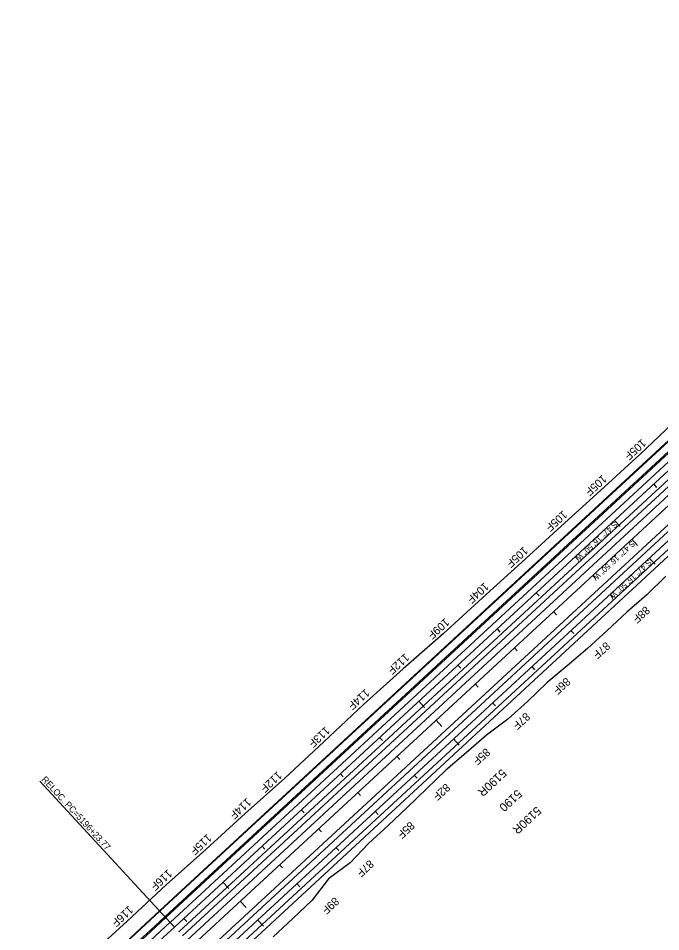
# Model space of a CAD drawing. Extents: x 2160876 to 2175625, y 601634 to 617693.
# Drawn here: x 2170102 to 2171308, y 612093 to 613806 of the extents above; entities that cross this region are included whole.
import ezdxf

# ---------------------------------------------------------------- set-up
doc = ezdxf.new("R2010")
doc.units = 0
for name, color, linetype in [('RD_HC_Cl', 7, 'Continuous'), ('RD_HC_CL_Rel', 7, 'Continuous'), ('RD_HC_Data', 7, 'Continuous'), ('RD_HC_Data_Rel', 7, 'Continuous'), ('RD_HC_Data_Tic', 7, 'Continuous'), ('RD_HC_Data_Tic_Rel', 7, 'Continuous'), ('RD_HC_TX_Rel_Sta50', 7, 'Continuous'), ('RD_HC_TX_Sta50', 7, 'Continuous'), ('RD_PD_CstnLmt', 7, 'Continuous'), ('RD_PD_Final_LnLine', 7, 'Continuous'), ('RD_PD_Final_TrvlWay', 7, 'Continuous'), ('RD_PD_GR', 7, 'Continuous'), ('RD_PD_MedBWall', 7, 'Continuous')]:
    doc.layers.add(name, color=color, linetype=linetype)

msp = doc.modelspace()

# ---------------------------------------------------------------- linework, layer by layer
at = {"layer": 'RD_HC_Cl'}
msp.add_line((2172239.9, 613739.9), (2163704.8, 605858.6), dxfattribs=at)
at = {"layer": 'RD_HC_CL_Rel'}
for p, q in [((2172207.3, 613775.1), (2170395.2, 612101.8)), ((2172272.5, 613704.6), (2170460.3, 612031.3))]:
    msp.add_line(p, q, dxfattribs=at)
msp.add_arc((2245020.2, 531286.6), 110000, 132.719474, 133.338342, dxfattribs=at)
at = {"layer": 'RD_HC_Data_Rel'}
msp.add_line((2170142.5, 612375.5), (2170395.2, 612101.8), dxfattribs=at)
at = {"layer": 'RD_HC_Data_Tic'}
for p, q in [((2171253.4, 612828.9), (2171264.2, 612817.2)), ((2171179.9, 612761.1), (2171185.3, 612755.2)), ((2171106.4, 612693.2), (2171111.8, 612687.3)), ((2171032.9, 612625.4), (2171038.4, 612619.5)), ((2170959.5, 612557.5), (2170964.9, 612551.7)), ((2170886, 612489.7), (2170896.9, 612477.9)), ((2170812.5, 612421.9), (2170818, 612416)), ((2170739.1, 612354), (2170744.5, 612348.1)), ((2170665.6, 612286.2), (2170671, 612280.3)), ((2170592.1, 612218.3), (2170597.6, 612212.5)), ((2170518.7, 612150.5), (2170529.5, 612138.7))]:
    msp.add_line(p, q, dxfattribs=at)
at = {"layer": 'RD_HC_Data_Tic_Rel'}
for p, q in [((2171294.3, 612932), (2171299.7, 612926.1)), ((2171220.8, 612864.2), (2171231.6, 612852.4)), ((2171147.3, 612796.3), (2171152.7, 612790.5)), ((2171285.9, 612793.6), (2171296.8, 612781.9)), ((2171073.9, 612728.5), (2171079.3, 612722.6)), ((2171212.4, 612725.8), (2171217.9, 612719.9)), ((2171000.4, 612660.7), (2171005.8, 612654.8)), ((2171139, 612658), (2171144.4, 612652.1)), ((2170926.9, 612592.8), (2170932.3, 612586.9)), ((2171065.5, 612590.1), (2171070.9, 612584.2)), ((2170853.4, 612525), (2170864.3, 612513.2)), ((2170992, 612522.3), (2170997.5, 612516.4)), ((2170780, 612457.1), (2170785.4, 612451.3)), ((2170918.6, 612454.4), (2170929.4, 612442.7)), ((2170706.5, 612389.3), (2170711.9, 612383.4)), ((2170845.1, 612386.6), (2170850.5, 612380.7)), ((2170633, 612321.4), (2170638.5, 612315.6)), ((2170771.6, 612318.8), (2170777.1, 612312.9)), ((2170559.6, 612253.6), (2170565, 612247.7)), ((2170698.2, 612250.9), (2170703.6, 612245)), ((2170486.1, 612185.8), (2170497, 612174)), ((2170624.7, 612183.1), (2170630.1, 612177.2)), ((2170412.6, 612117.9), (2170418.1, 612112)), ((2170551.2, 612115.2), (2170562.1, 612103.5))]:
    msp.add_line(p, q, dxfattribs=at)
at = {"layer": 'RD_PD_CstnLmt'}
for p, q in [((2171341.1, 613056.4), (2171268.6, 612987.6)), ((2171268.6, 612987.6), (2171194.8, 612920.4)), ((2171194.8, 612920.4), (2171120.6, 612853.6)), ((2171120.6, 612853.6), (2171047, 612786.1)), ((2171047, 612786.1), (2170973.3, 612718.7)), ((2170973.3, 612718.7), (2170899.3, 612651.6)), ((2170899.3, 612651.6), (2170824.3, 612585.7)), ((2170824.3, 612585.7), (2170749.7, 612519.3)), ((2170749.7, 612519.3), (2170675.7, 612448.7)), ((2170675.7, 612448.7), (2170602.4, 612380.9)), ((2170602.4, 612380.9), (2170527.8, 612314.5)), ((2170527.8, 612314.5), (2170453.8, 612247.3)), ((2170453.8, 612247.3), (2170379.5, 612180.7)), ((2170379.5, 612180.7), (2170306.3, 612112.7)), ((2170306.3, 612112.7), (2170232.5, 612045.5))]:
    msp.add_line(p, q, dxfattribs=at)
msp.add_lwpolyline([(2171317.4, 612759.5), (2171281.4, 612724.8), (2171243.7, 612691.9), (2171207.3, 612657.7), (2171170.3, 612624.1), (2171132.3, 612591.5), (2171093.8, 612559.5), (2171057.6, 612524.9), (2171020.5, 612491.5), (2170980.4, 612461.2), (2170942.5, 612428.5), (2170904.5, 612395.9), (2170868.6, 612361.2), (2170832.6, 612326.4), (2170796, 612292.4), (2170759.1, 612258.7), (2170724.9, 612221.9), (2170684.4, 612192.1), (2170653.3, 612152.1), (2170617.1, 612117.6), (2170580.6, 612083.5)], dxfattribs=at)
at = {"layer": 'RD_PD_Final_LnLine'}
for p, q in [((2172179.3, 613805.5), (2170367.1, 612132.2)), ((2172180, 613804.8), (2170367.8, 612131.4)), ((2172199.2, 613784), (2170387, 612110.6)), ((2172207.3, 613775.1), (2170395.2, 612101.8)), ((2172215.5, 613766.3), (2170403.3, 612093)), ((2172264.3, 613713.4), (2170452.2, 612040.1)), ((2172272.5, 613704.6), (2170460.3, 612031.3)), ((2172261.1, 613677.8), (2170468.4, 612022.5))]:
    msp.add_line(p, q, dxfattribs=at)
for radius in [110041.3, 110040.3, 110012, 110000]:
    msp.add_arc((2245020.2, 531286.6), radius, 132.719474, 133.338342, dxfattribs=at)
at = {"layer": 'RD_PD_Final_TrvlWay'}
for p, q in [((2172191, 613792.8), (2170378.9, 612119.4)), ((2172222.2, 613759), (2170410.1, 612085.6)), ((2172257.5, 613720.8), (2170445.4, 612047.4)), ((2172287.4, 613688.4), (2170475.2, 612015.1))]:
    msp.add_line(p, q, dxfattribs=at)
msp.add_arc((2245020.2, 531286.6), 110024, 132.719474, 133.338342, dxfattribs=at)
at = {"layer": 'RD_PD_GR'}
msp.add_line((2170418.2, 612076.8), (2171614.4, 613181.4), dxfattribs=at)
at = {"layer": 'RD_PD_MedBWall'}
for p, q in [((2172189.5, 613794.5), (2170377.3, 612121.1)), ((2172191, 613792.8), (2170378.9, 612119.4))]:
    msp.add_line(p, q, dxfattribs=at)
for radius in [110026.3, 110024]:
    msp.add_arc((2245020.2, 531286.6), radius, 132.719474, 133.338342, dxfattribs=at)

# ---------------------------------------------------------------- texts
at = {"layer": 'RD_HC_Data'}
msp.add_text('S 47° 16\' 50" W', height=10.8, rotation=222.7195, dxfattribs=at).set_placement((2171253.1, 612826.7))
at = {"layer": 'RD_HC_Data_Rel'}
for s, height, rotation, p in [('S 47° 16\' 50" W', 10.8, 222.7195, (2171220.4, 612862.8)), ('S 47° 16\' 50" W', 10.8, 222.7195, (2171284.4, 612791.3)), ('RELOC. PC=5196+23.77', 12, 312.7195, (2170144.9, 612377.7))]:
    msp.add_text(s, height=height, rotation=rotation, dxfattribs=at).set_placement(p)
at = {"layer": 'RD_HC_TX_Rel_Sta50'}
for p in [(2171009.3, 612399.4), (2171074.4, 612328.9)]:
    msp.add_text('5190R', height=16, rotation=222.7195, dxfattribs=at).set_placement(p)
at = {"layer": 'RD_HC_TX_Sta50'}
msp.add_text('5190', height=16, rotation=222.7195, dxfattribs=at).set_placement((2171038.1, 612360.6))
at = {"layer": 'RD_PD_CstnLmt'}
for s, rotation, p in [('105F', 222.3607, (2171271.9, 613017.7)), ('105F', 222.2822, (2171198.1, 612950.5)), ('105F', 222.2037, (2171124, 612883.6)), ('105F', 222.1253, (2171050.4, 612816.1)), ('104F', 222.0468, (2170976.8, 612748.7)), ('88F', 222.2037, (2171278.9, 612704.4)), ('109F', 221.9683, (2170902.8, 612681.7)), ('87F', 222.1253, (2171204.4, 612637.5)), ('112F', 221.8898, (2170827.8, 612615.8)), ('86F', 222.0468, (2171129.9, 612570.7)), ('114F', 221.8113, (2170753.3, 612549.3)), ('87F', 221.9683, (2171054.1, 612504.9)), ('113F', 222.9825, (2170678.6, 612478.8)), ('85F', 221.8898, (2170979.3, 612438.3)), ('112F', 222.904, (2170588.5, 612394.8)), ('82F', 221.8113, (2170904.3, 612372)), ('114F', 222.8255, (2170530.8, 612344.6)), ('85F', 222.9825, (2170837.3, 612300.6)), ('115F', 222.747, (2170456.9, 612277.4)), ('87F', 222.904, (2170760.8, 612228.6)), ('116F', 222.6685, (2170382.6, 612210.8)), ('89F', 222.8255, (2170695.6, 612158.8)), ('116F', 222.59, (2170309.5, 612142.8))]:
    msp.add_text(s, height=15, rotation=rotation, dxfattribs=at).set_placement(p)

doc.saveas('drawing.dxf')
